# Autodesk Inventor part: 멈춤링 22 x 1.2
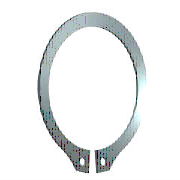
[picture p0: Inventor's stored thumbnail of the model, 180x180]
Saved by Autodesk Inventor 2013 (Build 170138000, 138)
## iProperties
IsCustomPart: 0
Company: 한국ATC센터
Created: 2009-02
Part Number: 멈춤링 22 x 1.2
Material: Steel, Mild
Description: 리테이닝 링(C형)
Document SubType Name: Modeling
Standard: KS B 1336
Designer: KYOUNG IL JANG
Standards Organization: KS
Language: ko-KR
Size Designation: 22 x 1.2
Categories: <MemberInstance><Categories><Category DisplayName="샤프트 부품" InternalName="7f7aeb1f-a693-4053-b835-cee3144e0d98" Mnemonic="SHFT"><Category DisplayName="써클립" Inter
Density: 7.86 g/cm^3
Mass: 1.82859 g
Surface Area: 5.91219 cm^2
Volume: 0.232645 cm^3
Author: KYOUNG IL JANG
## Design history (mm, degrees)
sketch "스케치1"
  geometry: L1 (-6, 0)-(6, 0) reference; L2 (0, 20.189)-(0, -80.536) reference; L3 (-48.09, 0)-(48.09, 0) reference; L4 (-0.5, -21.488)-(-0.5, -25.588); L5 (-0.5, -6.54)-(-0.5, -13.29); L6 (-2.795, 2.7)-(3.672, 2.7); L7 (0.5, -6.54)-(0.5, -13.29); L8 (0.5, -21.488)-(0.5, -25.588); C1 r 1 at (-2, -23.437); C2 r 1 at (2, -23.437); A1 r 10.5 centre (0, -11) between (0.5, -21.488) and (-0.5, -21.488); A2 r 13.025 centre (0, -10.325) between (5.149, -22.289) and (-5.149, -22.289); A3 r 14.597 centre (0, -11) between (-2.318, -25.411) and (-0.5, -25.588); A4 r 2 centre (-2, -23.437) between (-3.97, -23.781) and (-2.318, -25.411); A5 r 2 centre (-5.94, -24.126) between (-3.97, -23.781) and (-5.149, -22.289); A6 r 2 centre (5.94, -24.126) between (5.149, -22.289) and (3.97, -23.781); A7 r 2 centre (2, -23.437) between (2.318, -25.411) and (3.97, -23.781); A8 r 14.597 centre (0, -11) between (0.5, -25.588) and (2.318, -25.411)
  constraints: 16 point on circle, 12 end point, 10 centre point, 9 symmetric about line, 5 point on line, 4 tangent, 3 coincident, 2 horizontal, 1 perpendicular, 1 vertical, 5 other
  dimensions: "d0" = 21 diameter of A1 (= ND); "d1" = 4.1 distance of L4.end L4.start (= SRB2); "d6" = 0.5 distance between parallel lines of L2 L5 (= 0.25 x SD5); "d7" = 2.7 distance between parallel lines of L6 L3 (= SRB1); "d8" = 0.675 distance of A1.centre A2.centre (= 0.25 x SRB1); "d9" = 2 radius of A4 (= SD5); "d10" = 2 radius of A5 (= SD5); "d11" = 1.5 distance from line of L4 A4.centre (= 0.75 x SD5); "d12" = 2 diameter of C1 (= SD5); "d13" = 2 diameter of C2 (= SD5); "d14" = 11 distance from line of A1.centre L1 (= 0.5 x WD)
extrude "본체" new body sketch "스케치1" distance "d2" = 1.2 (= SD); taper "d3" = 0 deg
workaxis "Work Axis1"
workplane "Work Plane1"
body "Solid1"
other parameters: "WD" = 22 (= WDMIN) [user parameter; used in 1 equation term], "SD" = 1.2 [user parameter; used in 1 equation term], "SRB1" = 2.7 [user parameter; used in 2 equation terms], "ND" = 21 [user parameter; used in 1 equation term], "SRB2" = 4.1 [user parameter; used in 1 equation term], "SD5" = 2 [user parameter; used in 6 equation terms], "d15" = 0, "d16" = 0, "d17" = 0, "d41" = 0, "d42" = 0, "WDMIN" = 22 [user parameter; used in 1 equation term], "SD3" = 20.5 [user parameter], "WDMAX" = 24 [user parameter]
